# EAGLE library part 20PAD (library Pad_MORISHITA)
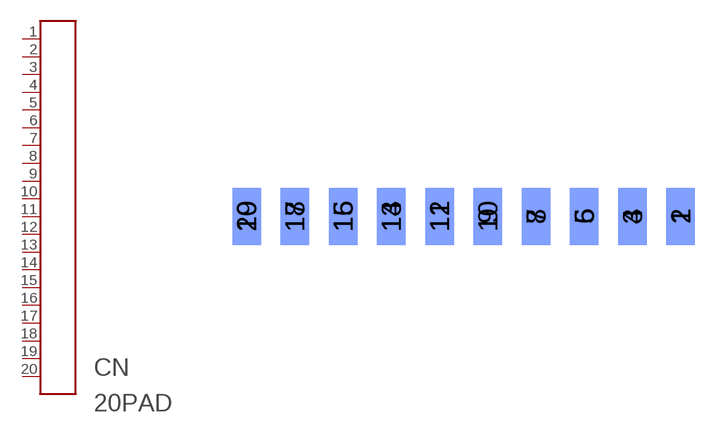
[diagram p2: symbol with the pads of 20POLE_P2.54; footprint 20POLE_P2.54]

Designator prefix CN

## 20PAD-2.54  [20POLE_P2.54]
1  P$1
2  P$2
3  P$3
4  P$4
5  P$5
6  P$6
7  P$7
8  P$8
9  P$9
10  P$10
11  P$11
12  P$12
13  P$13
14  P$14
15  P$15
16  P$16
17  P$17
18  P$18
19  P$19
20  P$20

## Footprint 20POLE_P2.54 (pad centres in mm)
smd 1.5 x 3: 1 11.43,0; 3 8.89,0; 5 6.35,0; 7 3.81,0; 9 1.27,0; 11 -1.27,0; 13 -3.81,0; 15 -6.35,0; 17 -8.89,0; 19 -11.43,0
smd 1.5 x 3 bottom: 2 11.43,0; 4 8.89,0; 6 6.35,0; 8 3.81,0; 10 1.27,0; 12 -1.27,0; 14 -3.81,0; 16 -6.35,0; 18 -8.89,0; 20 -11.43,0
